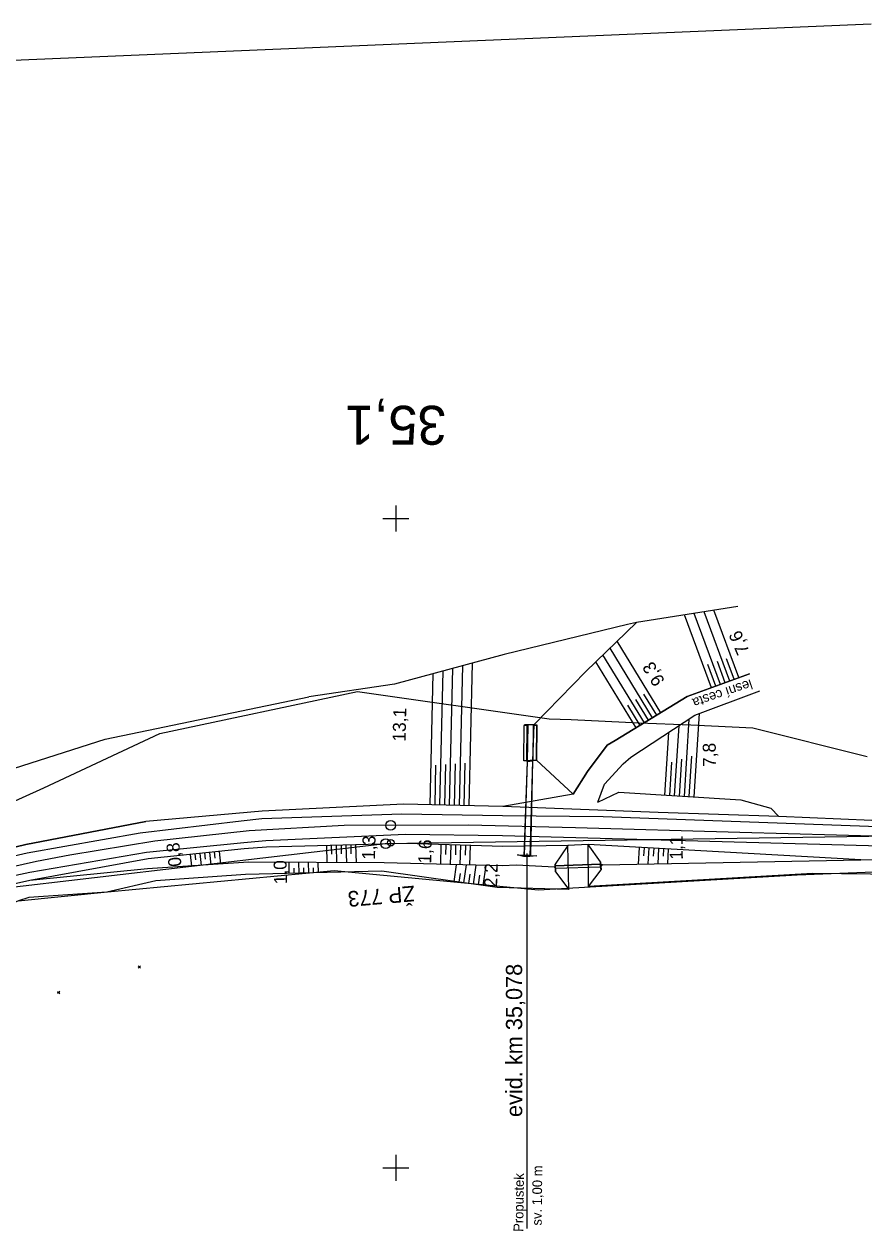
# Model space of a CAD drawing. Extents: x -806456 to -805395, y -1150847 to -1150506.
# Drawn here: x -805957.2 to -805828, y -1150709.7 to -1150523.9 of the extents above; entities that cross this region are included whole.
import ezdxf

# ---------------------------------------------------------------- set-up
doc = ezdxf.new("R2010")
doc.units = 0
for name, color, linetype in [('0381KM032-037P - Vrstva 1', 7, 'Continuous'), ('0381KM032-037P - Vrstva 19', 7, 'Continuous'), ('0381KM032-037P - Vrstva 4', 7, 'Continuous'), ('0381KM032-037P - Vrstva 48', 7, 'Continuous'), ('0381KM032-037P - Vrstva 49', 7, 'Continuous'), ('0381KM032-037P - Vrstva 51', 7, 'Continuous'), ('0381KM032-037P - Vrstva 7', 7, 'Continuous'), ('formát', 7, 'Continuous'), ('hran DP - hran DP', 7, 'Continuous'), ('krizky_1000 - Vrstva 1', 7, 'Continuous'), ('vyt_sit - polygon', 7, 'Continuous'), ('vyt_sit - stávající', 7, 'Continuous')]:
    doc.layers.add(name, color=color, linetype=linetype)

msp = doc.modelspace()

# ---------------------------------------------------------------- linework, layer by layer
at = {"layer": '0381KM032-037P - Vrstva 1'}
for points in [[(-805907.99, -1150647.29), (-805922.59, -1150648.1), (-805937.12, -1150649.71), (-805950.23, -1150651.85), (-805955.36, -1150652.84)], [(-805872.37, -1150647.65), (-805888.81, -1150647.23), (-805907.99, -1150647.29)], [(-805647.61, -1150654.06), (-805666.7, -1150653.55), (-805695.88, -1150652.69), (-805700.7, -1150652.54), (-805736.3, -1150651.55), (-805773.14, -1150650.48), (-805809.82, -1150649.4), (-805847.04, -1150648.36), (-805872.37, -1150647.65)], [(-805955.36, -1150652.84), (-805972.27, -1150656.66), (-805989.76, -1150661.17)]]:
    msp.add_lwpolyline(points, dxfattribs=at)
at = {"layer": '0381KM032-037P - Vrstva 19'}
for p, q in [((-805880.33, -1150637.33), (-805880.27, -1150631.9)), ((-805880.27, -1150631.9), (-805880.21, -1150631.81)), ((-805879.77, -1150631.9), (-805880.27, -1150631.9)), ((-805879.71, -1150631.81), (-805880.21, -1150631.81)), ((-805878.75, -1150631.78), (-805879.71, -1150631.81)), ((-805878.81, -1150631.82), (-805878.31, -1150631.82)), ((-805878.75, -1150631.78), (-805878.25, -1150631.78)), ((-805878.37, -1150637.24), (-805878.31, -1150631.82)), ((-805878.31, -1150631.82), (-805878.25, -1150631.78)), ((-805879.83, -1150637.33), (-805880.33, -1150637.33)), ((-805879.78, -1150637.42), (-805880.28, -1150652.07)), ((-805879.78, -1150637.42), (-805880.23, -1150651.86)), ((-805878.87, -1150637.24), (-805879.83, -1150637.33)), ((-805878.96, -1150637.32), (-805879.78, -1150637.42)), ((-805879.78, -1150637.42), (-805878.96, -1150637.32)), ((-805878.96, -1150637.32), (-805879.38, -1150652.05)), ((-805878.96, -1150637.32), (-805879.27, -1150651.81)), ((-805878.87, -1150637.24), (-805878.37, -1150637.24)), ((-805879.79, -1150709.36), (-805879.79, -1150651.59)), ((-805868.51, -1150653.23), (-805875.47, -1150653.52)), ((-805875.46, -1150653.52), (-805868.51, -1150653.23)), ((-805875.43, -1150653.86), (-805868.49, -1150653.67)), ((-805875.43, -1150653.87), (-805868.5, -1150653.67))]:
    msp.add_line(p, q, dxfattribs=at)
for points in [[(-805879.78, -1150637.42), (-805879.83, -1150637.33), (-805879.77, -1150631.9), (-805879.71, -1150631.81)], [(-805878.81, -1150631.82), (-805878.75, -1150631.78), (-805878.96, -1150637.32), (-805878.87, -1150637.24)], [(-805879.38, -1150652.05), (-805880.28, -1150652.07), (-805881.3, -1150651.8), (-805878.28, -1150651.94)]]:
    msp.add_lwpolyline(points, close=True, dxfattribs=at)
for points in [[(-805880.28, -1150652.07), (-805880.23, -1150651.86), (-805879.27, -1150651.81), (-805879.38, -1150652.05)], [(-805875.47, -1150653.27), (-805875.43, -1150654.45), (-805875.43, -1150653.87), (-805875.43, -1150653.86), (-805875.47, -1150653.52), (-805875.46, -1150653.52), (-805875.47, -1150653.27)], [(-805868.49, -1150652.87), (-805868.42, -1150654.14), (-805868.5, -1150653.67), (-805868.49, -1150653.67), (-805868.51, -1150653.23), (-805868.51, -1150653.23), (-805868.49, -1150652.87)]]:
    msp.add_lwpolyline(points, dxfattribs=at)
at = {"layer": '0381KM032-037P - Vrstva 4'}
for points in [[(-805734.36, -1150649.18), (-805786.14, -1150647.68), (-805826.72, -1150646.54), (-805841.05, -1150645.92), (-805859.62, -1150645.3), (-805883.54, -1150644.38), (-805898.84, -1150644.02), (-805920.59, -1150645.08)], [(-805920.59, -1150645.08), (-805938.49, -1150646.69), (-805957, -1150650.24), (-805973.18, -1150654.13), (-805996.94, -1150660.52), (-806010.57, -1150664.04), (-806045.29, -1150673.07), (-806070.44, -1150679.45), (-806076.44, -1150680.94), (-806080.95, -1150682.04), (-806094.16, -1150685.34), (-806107.83, -1150689.09)], [(-805687.98, -1150651.47), (-805728.71, -1150650.4), (-805771.75, -1150649.09), (-805796.82, -1150648.44), (-805827.25, -1150647.42), (-805868.08, -1150645.94), (-805883.57, -1150645.79), (-805899.1, -1150645.56), (-805920.66, -1150646.24), (-805923.83, -1150646.61)], [(-805923.83, -1150646.61), (-805939.39, -1150648.49), (-805956.78, -1150651.56), (-805972.77, -1150655.27), (-805996.74, -1150661.47), (-806010.38, -1150665.11), (-806045.15, -1150673.98), (-806070.28, -1150680.43), (-806094.02, -1150686.67), (-806107.78, -1150690.05)], [(-805688.15, -1150654.42), (-805728.36, -1150653.2), (-805771.94, -1150652.19), (-805796.53, -1150651.28), (-805827.23, -1150650.42), (-805883.58, -1150648.86), (-805898.54, -1150648.68), (-805920.02, -1150649.65), (-805923.42, -1150649.97)], [(-805923.37, -1150650.9), (-805938.15, -1150652.42), (-805956.35, -1150655.74), (-805972.37, -1150659.35), (-805995.12, -1150665.03), (-806009.04, -1150668.86), (-806027.1, -1150673.31), (-806034.62, -1150675.7), (-806043.91, -1150677.85), (-806068.97, -1150684.48)], [(-805923.42, -1150649.97), (-805938.4, -1150651.47), (-805956.35, -1150654.55), (-805972.44, -1150657.98), (-805995.68, -1150664.21)], [(-805687.42, -1150655.93), (-805728.29, -1150654.47), (-805772.22, -1150653.64), (-805796.51, -1150653.02), (-805828.44, -1150652.6), (-805870.39, -1150650.22), (-805873.51, -1150650.39), (-805883.54, -1150650.55), (-805898.37, -1150650.08), (-805919.92, -1150650.63), (-805923.37, -1150650.9)]]:
    msp.add_lwpolyline(points, dxfattribs=at)
at = {"layer": '0381KM032-037P - Vrstva 48'}
for p, q in [((-805850.02, -1150625.56), (-805854.06, -1150614.63)), ((-805848.61, -1150625.04), (-805852.55, -1150614.39)), ((-805847.21, -1150624.52), (-805851.04, -1150614.15)), ((-805851.43, -1150626.08), (-805855.57, -1150614.87)), ((-805860.47, -1150630.7), (-805867.02, -1150619.96)), ((-805859.19, -1150629.92), (-805865.92, -1150618.89)), ((-805861.75, -1150631.48), (-805868.13, -1150621.03)), ((-805847.91, -1150624.78), (-805849.08, -1150621.63)), ((-805894.73, -1150644.11), (-805894.25, -1150623.91)), ((-805893.23, -1150644.15), (-805892.74, -1150623.5)), ((-805891.73, -1150644.19), (-805891.23, -1150623.09)), ((-805890.23, -1150644.22), (-805889.72, -1150622.69)), ((-805888.73, -1150644.26), (-805888.21, -1150622.28)), ((-805863.03, -1150632.26), (-805869.23, -1150622.1)), ((-805850.72, -1150625.82), (-805851.95, -1150622.5)), ((-805849.32, -1150625.3), (-805850.51, -1150622.06)), ((-805859.83, -1150630.31), (-805861.82, -1150627.04)), ((-805862.39, -1150631.87), (-805864.28, -1150628.78)), ((-805861.11, -1150631.09), (-805863.05, -1150627.91)), ((-805855.59, -1150642.8), (-805854.83, -1150630.89)), ((-805854.09, -1150642.9), (-805853.28, -1150630.06)), ((-805858.59, -1150642.61), (-805857.97, -1150632.95)), ((-805857.09, -1150642.71), (-805856.4, -1150631.92)), ((-805854.84, -1150642.85), (-805854.45, -1150636.61)), ((-805893.98, -1150644.13), (-805893.83, -1150638)), ((-805892.48, -1150644.17), (-805892.33, -1150637.91)), ((-805890.98, -1150644.2), (-805890.83, -1150637.81)), ((-805889.48, -1150644.24), (-805889.33, -1150637.71)), ((-805857.84, -1150642.66), (-805857.51, -1150637.55)), ((-805856.34, -1150642.76), (-805855.98, -1150637.08)), ((-805931.69, -1150651.75), (-805931.5, -1150653.53)), ((-805930.94, -1150651.68), (-805930.85, -1150652.58)), ((-805930.19, -1150651.6), (-805930.01, -1150653.44)), ((-805929.45, -1150651.52), (-805929.35, -1150652.46)), ((-805928.7, -1150651.45), (-805928.51, -1150653.34)), ((-805927.96, -1150651.37), (-805927.86, -1150652.33)), ((-805927.21, -1150651.29), (-805927.01, -1150653.25)), ((-805910.7, -1150650.4), (-805910.63, -1150653.02)), ((-805909.95, -1150650.38), (-805909.92, -1150651.7)), ((-805909.2, -1150650.36), (-805909.13, -1150653.02)), ((-805908.45, -1150650.34), (-805908.42, -1150651.68)), ((-805907.7, -1150650.32), (-805907.63, -1150653.02)), ((-805906.95, -1150650.3), (-805906.92, -1150651.66)), ((-805906.2, -1150650.28), (-805906.13, -1150653.02)), ((-805893.06, -1150650.25), (-805893.15, -1150653.26)), ((-805892.31, -1150650.27), (-805892.35, -1150651.78)), ((-805891.56, -1150650.3), (-805891.65, -1150653.3)), ((-805890.81, -1150650.32), (-805890.85, -1150651.82)), ((-805890.06, -1150650.34), (-805890.15, -1150653.34)), ((-805889.31, -1150650.37), (-805889.35, -1150651.86)), ((-805888.56, -1150650.39), (-805888.65, -1150653.38)), ((-805862.55, -1150650.67), (-805862.69, -1150653.23)), ((-805861.8, -1150650.71), (-805861.87, -1150651.96)), ((-805861.05, -1150650.75), (-805861.19, -1150653.2)), ((-805860.3, -1150650.79), (-805860.37, -1150651.99)), ((-805859.55, -1150650.84), (-805859.69, -1150653.17)), ((-805858.8, -1150650.88), (-805858.87, -1150652.02)), ((-805858.06, -1150650.92), (-805858.18, -1150653.15)), ((-805916.42, -1150654.68), (-805916.46, -1150653.01)), ((-805914.92, -1150654.65), (-805914.96, -1150653.01)), ((-805913.42, -1150654.61), (-805913.46, -1150653.01)), ((-805911.92, -1150654.57), (-805911.96, -1150653.01)), ((-805891.01, -1150655.91), (-805890.65, -1150653.33)), ((-805889.53, -1150656.12), (-805889.14, -1150653.37)), ((-805888.04, -1150656.33), (-805887.63, -1150653.41)), ((-805886.56, -1150656.54), (-805886.12, -1150653.45)), ((-805915.67, -1150654.66), (-805915.69, -1150653.84)), ((-805914.17, -1150654.63), (-805914.19, -1150653.82)), ((-805912.67, -1150654.59), (-805912.69, -1150653.8)), ((-805890.27, -1150656.01), (-805890.08, -1150654.68)), ((-805888.79, -1150656.22), (-805888.58, -1150654.8)), ((-805887.3, -1150656.44), (-805887.09, -1150654.93))]:
    msp.add_line(p, q, dxfattribs=at)
at = {"layer": '0381KM032-037P - Vrstva 49'}
for p, q in [((-805883.54, -1150644.38), (-805898.84, -1150644.02)), ((-805873.4, -1150657.16), (-805873.51, -1150650.39)), ((-805868.18, -1150653.33), (-805828.44, -1150652.6)), ((-805939.34, -1150668.9), (-805939.69, -1150669.26)), ((-805939.69, -1150668.9), (-805939.34, -1150669.25)), ((-805952.13, -1150672.84), (-805951.77, -1150673.19)), ((-805951.77, -1150672.84), (-805952.12, -1150673.19))]:
    msp.add_line(p, q, dxfattribs=at)
for points in [[(-805847.37, -1150613.56), (-805862.98, -1150616.05), (-805864.35, -1150616.33), (-805883.33, -1150620.98), (-805900.2, -1150625.5), (-805913.4, -1150627.48)], [(-805862.98, -1150616.05), (-805870.78, -1150623.59), (-805878.75, -1150631.78)], [(-805845.56, -1150623.91), (-805855.14, -1150627.45), (-805866.22, -1150634.21), (-805867.47, -1150634.93), (-805870.51, -1150638.97), (-805872.7, -1150642.46)], [(-805973.62, -1150650.67), (-805958.72, -1150638.45), (-805944.76, -1150634.02), (-805913.4, -1150627.48)], [(-805868.9, -1150643.71), (-805867.89, -1150640.94), (-805864.99, -1150637.81), (-805863.82, -1150636.79), (-805853.97, -1150630.32), (-805843.97, -1150626.57)], [(-805878.75, -1150631.78), (-805878.25, -1150631.78), (-805878.31, -1150631.82), (-805878.37, -1150637.24), (-805872.7, -1150642.46)], [(-805872.7, -1150642.46), (-805883.54, -1150644.38)], [(-805868.9, -1150643.71), (-805865.69, -1150642.16), (-805846.9, -1150643.36)], [(-805883.54, -1150644.38), (-805898.84, -1150644.02), (-805920.59, -1150645.08)], [(-805846.9, -1150643.36), (-805842.28, -1150644.6), (-805841.05, -1150645.92)], [(-805920.59, -1150645.08), (-805938.49, -1150646.69)], [(-805786.14, -1150647.68), (-805826.72, -1150646.54), (-805841.05, -1150645.92)], [(-806076.44, -1150680.94), (-806070.44, -1150679.45), (-806045.29, -1150673.07), (-806010.57, -1150664.04), (-805996.94, -1150660.52), (-805973.18, -1150654.13), (-805957, -1150650.24), (-805938.49, -1150646.69)], [(-805923.37, -1150650.9), (-805938.15, -1150652.42), (-805956.35, -1150655.74), (-805972.37, -1150659.35), (-805995.12, -1150665.03)], [(-805873.51, -1150650.39), (-805883.54, -1150650.55), (-805898.37, -1150650.08), (-805919.92, -1150650.63), (-805923.37, -1150650.9)], [(-805873.51, -1150650.39), (-805875.47, -1150653.27), (-805875.46, -1150653.52), (-805875.59, -1150653.71)], [(-805687.42, -1150655.93), (-805728.29, -1150654.47), (-805772.22, -1150653.64), (-805796.51, -1150653.02), (-805828.44, -1150652.6), (-805870.39, -1150650.22)], [(-805687.58, -1150660.02), (-805738.95, -1150663.31), (-805774.06, -1150657.65), (-805795.8, -1150655.14), (-805835.84, -1150654.7), (-805870.36, -1150656.71), (-805870.39, -1150650.22)], [(-805870.36, -1150656.71), (-805868.42, -1150654.14), (-805868.5, -1150653.67), (-805868.18, -1150653.33), (-805868.51, -1150653.23), (-805868.49, -1150652.87), (-805870.39, -1150650.22)], [(-805922.71, -1150652.93), (-805938.23, -1150653.94), (-805956.35, -1150655.74)], [(-805875.59, -1150653.71), (-805881.41, -1150653.41), (-805883.63, -1150653.51), (-805901.81, -1150653.03), (-805922.71, -1150652.93)], [(-805923.15, -1150654.86), (-805936.98, -1150655.81), (-805944.5, -1150657.57), (-805956.52, -1150658.37), (-805958.13, -1150658.91), (-805970.8, -1150664), (-805994.63, -1150670.19)], [(-805873.4, -1150657.16), (-805884.43, -1150656.84), (-805902.18, -1150654.32), (-805923.15, -1150654.86)], [(-805875.59, -1150653.71), (-805875.43, -1150653.87), (-805875.43, -1150654.45), (-805873.4, -1150657.16)]]:
    msp.add_lwpolyline(points, dxfattribs=at)
at = {"layer": '0381KM032-037P - Vrstva 51'}
for points in [[(-805872.7, -1150642.46), (-805870.51, -1150638.97), (-805867.47, -1150634.93), (-805866.22, -1150634.21), (-805855.14, -1150627.45), (-805845.56, -1150623.91)], [(-805867.47, -1150634.93), (-805866.22, -1150634.21), (-805855.14, -1150627.45), (-805845.56, -1150623.91)], [(-805864.99, -1150637.81), (-805863.82, -1150636.79), (-805853.97, -1150630.32), (-805843.97, -1150626.57)], [(-805872.7, -1150642.46), (-805870.51, -1150638.97), (-805867.47, -1150634.93)], [(-805868.9, -1150643.71), (-805867.89, -1150640.94), (-805864.99, -1150637.81)]]:
    msp.add_lwpolyline(points, dxfattribs=at)
at = {"layer": '0381KM032-037P - Vrstva 7'}
msp.add_line((-805900.84, -1150649.94), (-805900.74, -1150649.94), dxfattribs=at)
for centre, radius in [((-805900.8, -1150647.27), 0.75), ((-805900.79, -1150649.94), 0.5)]:
    msp.add_circle(centre, radius, dxfattribs=at)
at = {"layer": 'formát'}
msp.add_line((-805826.83, -1150523.88), (-806456.26, -1150550.6), dxfattribs=at)
at = {"layer": 'hran DP - hran DP'}
for p, q in [((-805936.34, -1150633.1), (-805905.92, -1150626.68)), ((-805905.92, -1150626.68), (-805876.4, -1150630.84)), ((-805876.4, -1150630.84), (-805873.01, -1150630.99)), ((-805873.01, -1150630.99), (-805862.56, -1150631.46)), ((-805954.21, -1150641.47), (-805936.34, -1150633.1)), ((-805862.56, -1150631.46), (-805854.6, -1150631.81)), ((-805854.6, -1150631.81), (-805845.04, -1150632.24)), ((-805845.04, -1150632.24), (-805827.46, -1150636.65)), ((-805984.31, -1150655.05), (-805954.21, -1150641.47)), ((-805909.49, -1150654.26), (-805944.43, -1150657.58)), ((-805878.04, -1150657.24), (-805909.49, -1150654.26)), ((-805838.22, -1150654.94), (-805878.04, -1150657.24)), ((-805807.41, -1150653.77), (-805838.22, -1150654.94)), ((-805944.43, -1150657.58), (-805958.14, -1150658.97))]:
    msp.add_line(p, q, dxfattribs=at)
at = {"layer": 'krizky_1000 - Vrstva 1'}
for points in [[(-805900, -1150598), (-805900, -1150602)], [(-805902, -1150600), (-805898, -1150600)], [(-805900, -1150698), (-805900, -1150702)], [(-805902, -1150700), (-805898, -1150700)]]:
    msp.add_lwpolyline(points, dxfattribs=at)
at = {"layer": 'vyt_sit - polygon'}
for p, q in [((-805901.58, -1150650.08), (-805759.38, -1150647.88)), ((-806002.92, -1150661.86), (-805901.58, -1150650.08))]:
    msp.add_line(p, q, dxfattribs=at)
at = {"layer": 'vyt_sit - stávající'}
msp.add_line((-805901.64, -1150650.08), (-805901.54, -1150650.08), dxfattribs=at)
msp.add_circle((-805901.58, -1150650.08), 0.756, dxfattribs=at)

# ---------------------------------------------------------------- texts
at = {"layer": '0381KM032-037P - Vrstva 19'}
for s, height, rotation, p in [('evid. km 35,078', 2.5, 90.0485, (-805880.55, -1150692.19)), ('sv. 1,00 m', 1.5, 89.3778, (-805877.56, -1150708.91)), (' Propustek', 1.5, 89.2433, (-805880.41, -1150710.44))]:
    msp.add_text(s, height=height, rotation=rotation, dxfattribs=at).set_placement(p)
at = {"layer": '0381KM032-037P - Vrstva 48'}
for s, rotation, p in [('7,6', 113.3216, (-805845.52, -1150620.49)), ('9,3', 121.2221, (-805858.53, -1150625.04)), ('13,1', 88.6293, (-805898.52, -1150634.39)), ('7,8', 90.583, (-805850.73, -1150638.27)), ('1,3', 88.4218, (-805903.23, -1150652.58)), ('1,6', 88.4623, (-805894.58, -1150653.18)), ('1,1', 90.4951, (-805855.82, -1150652.56)), ('0,8', 95.8667, (-805933, -1150653.53)), ('1,0', 91.4666, (-805916.75, -1150656.32)), ('2,2', 88.3753, (-805884.43, -1150656.84))]:
    msp.add_text(s, height=2, rotation=rotation, dxfattribs=at).set_placement(p)
at = {"layer": '0381KM032-037P - Vrstva 51'}
msp.add_text('lesní cesta', height=1.5, rotation=198.6145, dxfattribs=at).set_placement((-805845.41, -1150624.74))
at = {"layer": '0381KM032-037P - Vrstva 7'}
msp.add_text('35,1', height=6, rotation=180, dxfattribs=at).set_placement((-805892.22, -1150582.65))
at = {"layer": 'vyt_sit - stávající'}
msp.add_text('ŽP 773', height=2.4, rotation=185, dxfattribs=at).set_placement((-805897.19, -1150656.55))

doc.saveas('drawing.dxf')
